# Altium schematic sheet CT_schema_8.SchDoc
size 405 x 220 mm
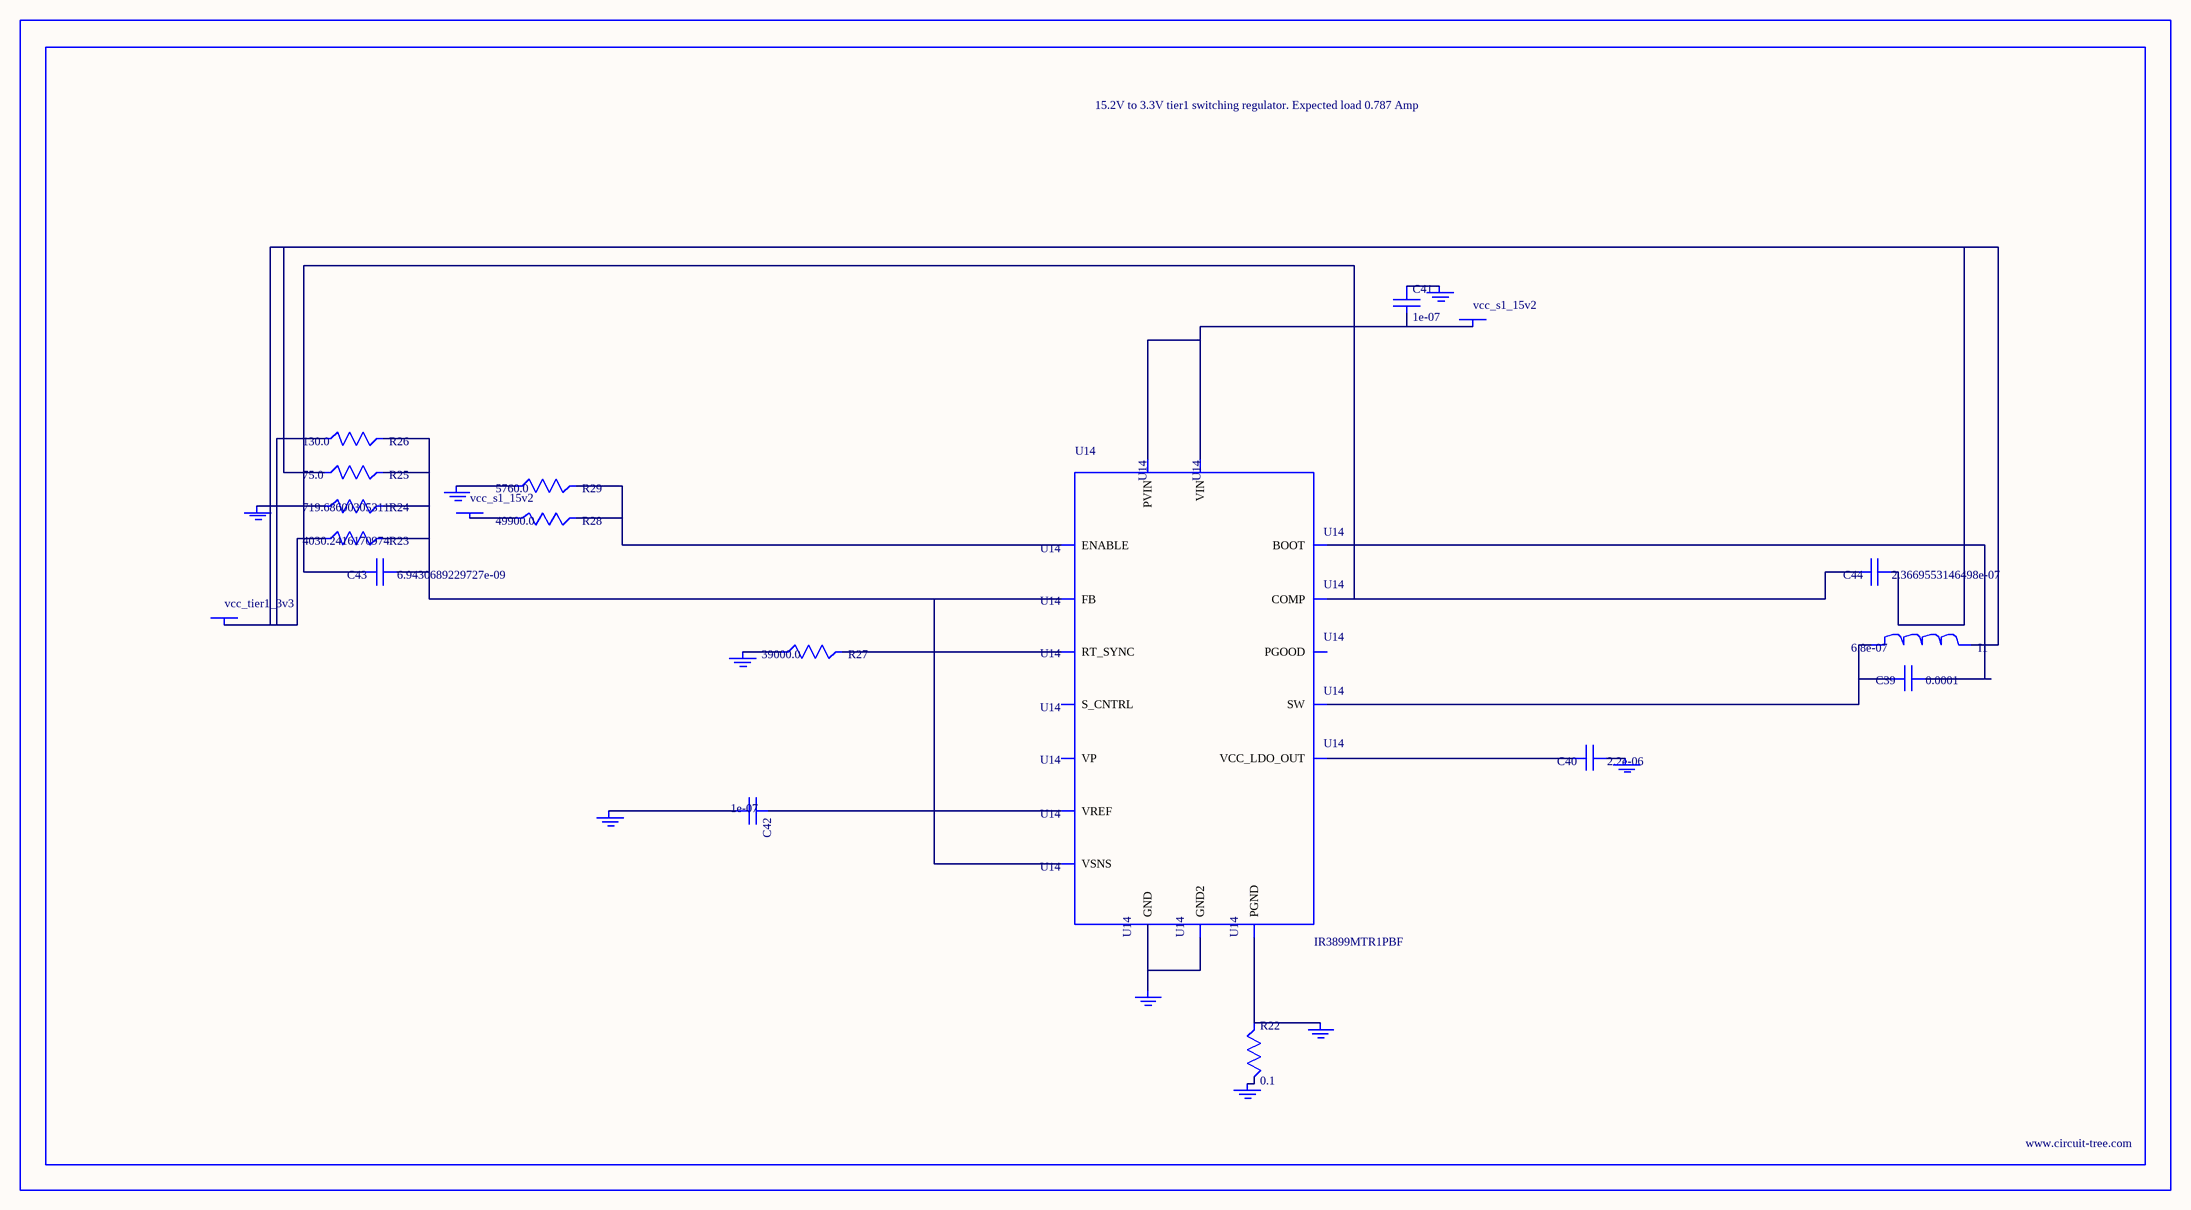
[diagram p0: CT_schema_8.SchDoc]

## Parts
BORDER7  (no value)
C39  0.0001  [C1210]
C40  2.2e-06  [C0603]
C41  1e-07  [C0402]
C42  1e-07  [C0402]
C43  6.9430689229727e-09  [R0603]
C44  2.3669553146498e-07  [R0603]
GND_INSTANCE_7_0  (no value)
GND_INSTANCE_7_1  (no value)
GND_INSTANCE_7_2  (no value)
GND_INSTANCE_7_3  (no value)
GND_INSTANCE_7_4  (no value)
GND_INSTANCE_7_5  (no value)
GND_INSTANCE_7_6  (no value)
GND_INSTANCE_7_7  (no value)
GND_INSTANCE_7_8  (no value)
I1  6.8e-07  [IND25X25CZ]
POWER_INSTANCE_7_0  vcc_s1_15v2
POWER_INSTANCE_7_1  vcc_s1_15v2
POWER_INSTANCE_7_2  vcc_tier1_3v3
R22  0.1  [R0603]
R23  4030.2416170974  [R0603]
R24  719.68600305311  [R0603]
R25  75.0  [R0603]
R26  130.0  [R0603]
R27  39000.0  [R0603]
R28  49900.0  [R0603]
R29  5760.0  [R0603]
U14  IR3899MTR1PBF  [IR3899MTR1PBF]

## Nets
NetC39_1: C39.1 U14.14(BOOT)
NetC39_2: C39.2 I1.1 U14.12(SW)
NetC40_1: C40.1 GND_INSTANCE_7_4.0(GND)
NetC40_2: C40.2 U14.10(VCC_LDO_OUT)
NetC41_1: C41.1 GND_INSTANCE_7_3.0(GND)
NetC41_2: C41.2 POWER_INSTANCE_7_0.0(PWR) U14.9(VIN) U14.13(PVIN)
NetC42_1: C42.1 U14.2(VREF)
NetC42_2: C42.2 GND_INSTANCE_7_1.0(GND)
NetC43_1: C43.1 R23.2 R24.2 R25.2 R26.2 U14.1(FB) U14.8(VSNS)
NetC43_2: C43.2 C44.2 U14.3(COMP)
NetC44_1: C44.1 I1.2 POWER_INSTANCE_7_2.0(PWR) R23.1 R25.1 R26.1
NetGND_INSTANCE_7_0_0: GND_INSTANCE_7_0.0(GND) R24.1
NetGND_INSTANCE_7_2_0: GND_INSTANCE_7_2.0(GND) R27.1
NetGND_INSTANCE_7_5_0: GND_INSTANCE_7_5.0(GND) R22.2
NetGND_INSTANCE_7_6_0: GND_INSTANCE_7_6.0(GND) R22.1 U14.11(PGND)
NetGND_INSTANCE_7_7_0: GND_INSTANCE_7_7.0(GND) R29.1
NetGND_INSTANCE_7_8_0: GND_INSTANCE_7_8.0(GND) U14.4(GND) U14.17(GND2)
NetPOWER_INSTANCE_7_1_0: POWER_INSTANCE_7_1.0(PWR) R28.1
NetR27_2: R27.2 U14.5(RT_SYNC)
NetR28_2: R28.2 R29.2 U14.15(ENABLE)

Not connected (* = marked no-connect by the designer): U14 6(S_CNTRL) 7(PGOOD) 16(VP)

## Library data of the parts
BORDER7 = BORDER_PAGE7
C39 = GRM32ER61A107ME20L
C40 = C0603C225K8RACTU
C41 C42 = C0402C104K3RACTU
C43 = C43
C44 = C44
GND_INSTANCE_7_0-GND_INSTANCE_7_8 = GND
I1 = IHLP2525CZERR68M01
POWER_INSTANCE_7_0-POWER_INSTANCE_7_2 = PWR
R22 = ERJ-3RSFR10V
R23 = R23
R24 = R24
R25 = RC0603JR-0775RL
R26 = RC0603JR-07130RL
R27 = RC0603JR-0739KL
R28 = RC0603FR-0749K9
R29 = ERJ-3EKF5760V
